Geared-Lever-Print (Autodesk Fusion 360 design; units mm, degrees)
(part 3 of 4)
sketch "Restore cam service opening after obsolete bore closure" plane through (23.9, 0, 0) normal (1, 0, 0) x axis (0, 0, -1)
  line L1 (-42.2047, 46.7373) -> (-43.8497, 47.5044)
  line L2 (-40.5875, 45.9133) -> (-42.2047, 46.7373)
  line L3 (-39, 45.0333) -> (-40.5875, 45.9133)
  line L4 (-37.4442, 44.0985) -> (-39, 45.0333)
  line L5 (-35.922, 43.11) -> (-37.4442, 44.0985)
  line L6 (-34.4352, 42.0689) -> (-35.922, 43.11)
  line L7 (-32.9856, 40.9766) -> (-34.4352, 42.0689)
  line L8 (-31.575, 39.8343) -> (-32.9856, 40.9766)
  line L9 (-30.2052, 38.6435) -> (-31.575, 39.8343)
  line L10 (-28.8778, 37.4057) -> (-30.2052, 38.6435)
  line L11 (-27.5943, 36.1222) -> (-28.8778, 37.4057)
  line L12 (-26.3565, 34.7948) -> (-27.5943, 36.1222)
  line L13 (-25.1657, 33.425) -> (-26.3565, 34.7948)
  line L14 (-24.0234, 32.0144) -> (-25.1657, 33.425)
  line L15 (-22.9311, 30.5648) -> (-24.0234, 32.0144)
  line L16 (-21.89, 29.078) -> (-22.9311, 30.5648)
  line L17 (-20.9015, 27.5558) -> (-21.89, 29.078)
  line L18 (-19.9667, 26) -> (-20.9015, 27.5558)
  line L19 (-19.0867, 24.4125) -> (-19.9667, 26)
  line L20 (-18.2627, 22.7953) -> (-19.0867, 24.4125)
  line L21 (-17.4956, 21.1503) -> (-18.2627, 22.7953)
  line L22 (-16.7864, 19.4795) -> (-17.4956, 21.1503)
  line L23 (-16.136, 17.785) -> (-16.7864, 19.4795)
  line L24 (-15.5451, 16.0689) -> (-16.136, 17.785)
  line L25 (-15.0144, 14.3331) -> (-15.5451, 16.0689)
  line L26 (-14.5446, 12.5799) -> (-15.0144, 14.3331)
  line L27 (-14.1363, 10.8114) -> (-14.5446, 12.5799)
  line L28 (-13.79, 9.0297) -> (-14.1363, 10.8114)
  line L29 (-13.5061, 7.237) -> (-13.79, 9.0297)
  line L30 (-13.2849, 5.4355) -> (-13.5061, 7.237)
  line L31 (-13.1267, 3.6273) -> (-13.2849, 5.4355)
  line L32 (-13.0317, 1.8148) -> (-13.1267, 3.6273)
  line L33 (-13, 0) -> (-13.0317, 1.8148)
  line L34 (-13.0317, -1.8148) -> (-13, 0)
  line L35 (-13.1267, -3.6273) -> (-13.0317, -1.8148)
  line L36 (-13.2849, -5.4355) -> (-13.1267, -3.6273)
  line L37 (-13.5061, -7.237) -> (-13.2849, -5.4355)
  line L38 (-13.79, -9.0297) -> (-13.5061, -7.237)
  line L39 (-14.1363, -10.8114) -> (-13.79, -9.0297)
  line L40 (-14.5446, -12.5799) -> (-14.1363, -10.8114)
  line L41 (-15.0144, -14.3331) -> (-14.5446, -12.5799)
  line L42 (-15.5451, -16.0689) -> (-15.0144, -14.3331)
  line L43 (-16.136, -17.785) -> (-15.5451, -16.0689)
  line L44 (-16.7864, -19.4795) -> (-16.136, -17.785)
  line L45 (-17.4956, -21.1503) -> (-16.7864, -19.4795)
  line L46 (-18.2627, -22.7953) -> (-17.4956, -21.1503)
  line L47 (-19.0867, -24.4125) -> (-18.2627, -22.7953)
  line L48 (-19.9667, -26) -> (-19.0867, -24.4125)
  line L49 (-20.9015, -27.5558) -> (-19.9667, -26)
  line L50 (-21.89, -29.078) -> (-20.9015, -27.5558)
  line L51 (-22.9311, -30.5648) -> (-21.89, -29.078)
  line L52 (-24.0234, -32.0144) -> (-22.9311, -30.5648)
  line L53 (-25.1657, -33.425) -> (-24.0234, -32.0144)
  line L54 (-26.3565, -34.7948) -> (-25.1657, -33.425)
  line L55 (-27.5943, -36.1222) -> (-26.3565, -34.7948)
  line L56 (-28.8778, -37.4057) -> (-27.5943, -36.1222)
  line L57 (-30.2052, -38.6435) -> (-28.8778, -37.4057)
  line L58 (-31.575, -39.8343) -> (-30.2052, -38.6435)
  line L59 (-32.9856, -40.9766) -> (-31.575, -39.8343)
  line L60 (-34.4352, -42.0689) -> (-32.9856, -40.9766)
  line L61 (-35.922, -43.11) -> (-34.4352, -42.0689)
  line L62 (-37.4442, -44.0985) -> (-35.922, -43.11)
  line L63 (-39, -45.0333) -> (-37.4442, -44.0985)
  line L64 (-40.5875, -45.9133) -> (-39, -45.0333)
  line L65 (-42.2047, -46.7373) -> (-40.5875, -45.9133)
  line L66 (-43.8497, -47.5044) -> (-42.2047, -46.7373)
  line L67 (-54.4248, -23.7522) -> (-43.8497, -47.5044)
  line L68 (-53.6024, -23.3686) -> (-54.4248, -23.7522)
  line L69 (-52.7937, -22.9566) -> (-53.6024, -23.3686)
  line L70 (-52, -22.5167) -> (-52.7937, -22.9566)
  line L71 (-51.2221, -22.0493) -> (-52, -22.5167)
  line L72 (-50.461, -21.555) -> (-51.2221, -22.0493)
  line L73 (-49.7176, -21.0344) -> (-50.461, -21.555)
  line L74 (-48.9928, -20.4883) -> (-49.7176, -21.0344)
  line L75 (-48.2875, -19.9172) -> (-48.9928, -20.4883)
  line L76 (-47.6026, -19.3218) -> (-48.2875, -19.9172)
  line L77 (-46.9389, -18.7028) -> (-47.6026, -19.3218)
  line L78 (-46.2972, -18.0611) -> (-46.9389, -18.7028)
  line L79 (-45.6782, -17.3974) -> (-46.2972, -18.0611)
  line L80 (-45.0828, -16.7125) -> (-45.6782, -17.3974)
  line L81 (-44.5117, -16.0072) -> (-45.0828, -16.7125)
  line L82 (-43.9656, -15.2824) -> (-44.5117, -16.0072)
  line L83 (-43.445, -14.539) -> (-43.9656, -15.2824)
  line L84 (-42.9507, -13.7779) -> (-43.445, -14.539)
  line L85 (-42.4833, -13) -> (-42.9507, -13.7779)
  line L86 (-42.0434, -12.2063) -> (-42.4833, -13)
  line L87 (-41.6314, -11.3976) -> (-42.0434, -12.2063)
  line L88 (-41.2478, -10.5752) -> (-41.6314, -11.3976)
  line L89 (-40.8932, -9.7398) -> (-41.2478, -10.5752)
  line L90 (-40.568, -8.8925) -> (-40.8932, -9.7398)
  line L91 (-40.2725, -8.0344) -> (-40.568, -8.8925)
  line L92 (-40.0072, -7.1666) -> (-40.2725, -8.0344)
  line L93 (-39.7723, -6.29) -> (-40.0072, -7.1666)
  line L94 (-39.5682, -5.4057) -> (-39.7723, -6.29)
  line L95 (-39.395, -4.5149) -> (-39.5682, -5.4057)
  line L96 (-39.253, -3.6185) -> (-39.395, -4.5149)
  line L97 (-39.1424, -2.7177) -> (-39.253, -3.6185)
  line L98 (-39.0633, -1.8137) -> (-39.1424, -2.7177)
  line L99 (-39.0158, -0.9074) -> (-39.0633, -1.8137)
  line L100 (-39, 0) -> (-39.0158, -0.9074)
  line L101 (-39.0158, 0.9074) -> (-39, 0)
  line L102 (-39.0633, 1.8137) -> (-39.0158, 0.9074)
  line L103 (-39.1424, 2.7177) -> (-39.0633, 1.8137)
  line L104 (-39.253, 3.6185) -> (-39.1424, 2.7177)
  line L105 (-39.395, 4.5149) -> (-39.253, 3.6185)
  line L106 (-39.5682, 5.4057) -> (-39.395, 4.5149)
  line L107 (-39.7723, 6.29) -> (-39.5682, 5.4057)
  line L108 (-40.0072, 7.1666) -> (-39.7723, 6.29)
  line L109 (-40.2725, 8.0344) -> (-40.0072, 7.1666)
  line L110 (-40.568, 8.8925) -> (-40.2725, 8.0344)
  line L111 (-40.8932, 9.7398) -> (-40.568, 8.8925)
  line L112 (-41.2478, 10.5752) -> (-40.8932, 9.7398)
  line L113 (-41.6314, 11.3976) -> (-41.2478, 10.5752)
  line L114 (-42.0434, 12.2063) -> (-41.6314, 11.3976)
  line L115 (-42.4833, 13) -> (-42.0434, 12.2063)
  line L116 (-42.9507, 13.7779) -> (-42.4833, 13)
  line L117 (-43.445, 14.539) -> (-42.9507, 13.7779)
  line L118 (-43.9656, 15.2824) -> (-43.445, 14.539)
  line L119 (-44.5117, 16.0072) -> (-43.9656, 15.2824)
  line L120 (-45.0828, 16.7125) -> (-44.5117, 16.0072)
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extrude "Extrude47" cut sketch "Restore cam service opening after obsolete bore closure" along normal blind 12.2
work_plane "WorkPlane48" AlongDistance -15.4 ExtraOffset 0
sketch "Fill former M5 stop nut pocket" plane through (-15.4, 0, 0) normal (1, 0, 0) x axis (0, 0, -1)
  circle C1 centre (-79.6754, -33.9652) radius 4.9
extrude "Extrude48" add sketch "Fill former M5 stop nut pocket" along normal blind 6.4
work_plane "WorkPlane49" AlongDistance -36 ExtraOffset 0
sketch "Fill former M5 stop bore" plane through (-36, 0, 0) normal (1, 0, 0) x axis (0, 0, -1)
  circle C1 centre (-79.6754, -33.9652) radius 2.71
extrude "Extrude49" add sketch "Fill former M5 stop bore" along normal blind 27
work_plane "WorkPlane50" AlongDistance -36.1 ExtraOffset 0
sketch "M3 stop reinforcement bore" plane through (-36.1, 0, 0) normal (1, 0, 0) x axis (0, 0, -1)
  circle C1 centre (-79.6754, -33.9652) radius 1.7
extrude "Extrude50" cut sketch "M3 stop reinforcement bore" along normal blind 27.2
work_plane "WorkPlane51" AlongDistance -13.5 ExtraOffset 0
sketch "Captive M3 locknut stop pocket" plane through (-13.5, 0, 0) normal (1, 0, 0) x axis (0, 0, -1)
  line L1 (-82.5754, -32.2908) -> (-79.6754, -30.6165)
  line L2 (-82.5754, -35.6395) -> (-82.5754, -32.2908)
  line L3 (-79.6754, -37.3138) -> (-82.5754, -35.6395)
  line L4 (-76.7754, -35.6395) -> (-79.6754, -37.3138)
  line L5 (-76.7754, -32.2908) -> (-76.7754, -35.6395)
  line L6 (-79.6754, -30.6165) -> (-76.7754, -32.2908)
extrude "Extrude51" cut sketch "Captive M3 locknut stop pocket" along normal blind 4.6
work_plane "WorkPlane52" AlongDistance -15.4 ExtraOffset 0
sketch "Fill former M5 stop nut pocket (1)" plane through (-15.4, 0, 0) normal (1, 0, 0) x axis (0, 0, -1)
  circle C1 centre (-79.6754, 33.9652) radius 4.9
extrude "Extrude52" add sketch "Fill former M5 stop nut pocket (1)" along normal blind 6.4
work_plane "WorkPlane53" AlongDistance -36 ExtraOffset 0
sketch "Fill former M5 stop bore (1)" plane through (-36, 0, 0) normal (1, 0, 0) x axis (0, 0, -1)
  circle C1 centre (-79.6754, 33.9652) radius 2.71
extrude "Extrude53" add sketch "Fill former M5 stop bore (1)" along normal blind 27
work_plane "WorkPlane54" AlongDistance -36.1 ExtraOffset 0
sketch "M3 stop reinforcement bore (1)" plane through (-36.1, 0, 0) normal (1, 0, 0) x axis (0, 0, -1)
  circle C1 centre (-79.6754, 33.9652) radius 1.7
extrude "Extrude54" cut sketch "M3 stop reinforcement bore (1)" along normal blind 27.2
work_plane "WorkPlane55" AlongDistance -13.5 ExtraOffset 0
sketch "Captive M3 locknut stop pocket (1)" plane through (-13.5, 0, 0) normal (1, 0, 0) x axis (0, 0, -1)
  line L1 (-82.5754, 35.6395) -> (-79.6754, 37.3138)
  line L2 (-82.5754, 32.2908) -> (-82.5754, 35.6395)
  line L3 (-79.6754, 30.6165) -> (-82.5754, 32.2908)
  line L4 (-76.7754, 32.2908) -> (-79.6754, 30.6165)
  line L5 (-76.7754, 35.6395) -> (-76.7754, 32.2908)
  line L6 (-79.6754, 37.3138) -> (-76.7754, 35.6395)
extrude "Extrude55" cut sketch "Captive M3 locknut stop pocket (1)" along normal blind 4.6
work_plane "WorkPlane56" AlongDistance -17.5 ExtraOffset 0
sketch "Recess M3 locknut to keep bolt inside stop" plane through (-17.5, 0, 0) normal (1, 0, 0) x axis (0, 0, -1)
  line L1 (-82.5754, -32.2908) -> (-79.6754, -30.6165)
  line L2 (-82.5754, -35.6395) -> (-82.5754, -32.2908)
  line L3 (-79.6754, -37.3138) -> (-82.5754, -35.6395)
  line L4 (-76.7754, -35.6395) -> (-79.6754, -37.3138)
  line L5 (-76.7754, -32.2908) -> (-76.7754, -35.6395)
  line L6 (-79.6754, -30.6165) -> (-76.7754, -32.2908)
extrude "Extrude56" cut sketch "Recess M3 locknut to keep bolt inside stop" along normal blind 4.01
work_plane "WorkPlane57" AlongDistance -17.5 ExtraOffset 0
sketch "Recess M3 locknut to keep bolt inside stop (1)" plane through (-17.5, 0, 0) normal (1, 0, 0) x axis (0, 0, -1)
  line L1 (-82.5754, 35.6395) -> (-79.6754, 37.3138)
  line L2 (-82.5754, 32.2908) -> (-82.5754, 35.6395)
  line L3 (-79.6754, 30.6165) -> (-82.5754, 32.2908)
  line L4 (-76.7754, 32.2908) -> (-79.6754, 30.6165)
  line L5 (-76.7754, 35.6395) -> (-76.7754, 32.2908)
  line L6 (-79.6754, 37.3138) -> (-76.7754, 35.6395)
extrude "Extrude57" cut sketch "Recess M3 locknut to keep bolt inside stop (1)" along normal blind 4.01
work_plane "WorkPlane6" AlongDistance -7.2 ExtraOffset 0
sketch "Upright socket roof 45 degrees" plane through (0, -7.2, 0) normal (0, 1, 0) x axis (1, 0, 0)
  line L1 (-7.2, -196) -> (0, -196)
  line L2 (0, -203.2) -> (-7.2, -196)
  line L3 (0, -196) -> (0, -203.2)
extrude "Extrude5" cut sketch "Upright socket roof 45 degrees" along normal blind 14.4
work_plane "WorkPlane8" AlongDistance -7.2 ExtraOffset 0
sketch "Upright socket roof 45 degrees" plane through (0, -7.2, 0) normal (0, 1, 0) x axis (1, 0, 0)
  line L1 (7.2, -196) -> (0, -196)
  line L2 (0, -203.2) -> (7.2, -196)
  line L3 (0, -196) -> (0, -203.2)
extrude "Extrude7" cut sketch "Upright socket roof 45 degrees" along normal blind 14.4
work_plane "WorkPlane58" AlongDistance -36 ExtraOffset 0
sketch "Stock M5x14 mounting seat Z64" plane through (-36, 0, 0) normal (1, 0, 0) x axis (0, 0, -1)
  line L1 (-63, -70) -> (-63, -95)
  line L2 (-64, -70) -> (-63, -70)
  line L3 (-64, -95) -> (-64, -70)
  line L4 (-63, -95) -> (-64, -95)
extrude "Extrude58" add sketch "Stock M5x14 mounting seat Z64" along normal blind 12
work_plane "WorkPlane59" AlongDistance 62.9 ExtraOffset 0
sketch "Continue rail clearance through new seat" plane through (0, 0, 62.9) normal (0, 0, 1) x axis (1, 0, 0)
  circle C1 centre (-30, -85) radius 2.7
extrude "Extrude59" cut sketch "Continue rail clearance through new seat" along normal blind 1.2
work_plane "WorkPlane1" AlongDistance 50 ExtraOffset 0
sketch "Rail M5x14 DIN912 (-30, -1)" plane through (0, 0, 50) normal (0, 0, 1) x axis (1, 0, 0)
  circle C1 centre (-30, -85) radius 2.5
extrude "Extrude1" new body sketch "Rail M5x14 DIN912 (-30, -1)" along normal blind 14 bodies "HARDWARE Rail M5x14 DIN912 (-30, -1)"
work_plane "WorkPlane2" AlongDistance 64 ExtraOffset 0
sketch "Button head" plane through (0, 0, 64) normal (0, 0, 1) x axis (1, 0, 0)
  circle C1 centre (-30, -85) radius 4.25
extrude "Extrude2" add sketch "Button head" along normal blind 5
work_plane "WorkPlane60" AlongDistance -36 ExtraOffset 0
sketch "Stock M5x14 mounting seat Z64 (1)" plane through (-36, 0, 0) normal (1, 0, 0) x axis (0, 0, -1)
  line L1 (-63, 95) -> (-63, 70)
  line L2 (-64, 95) -> (-63, 95)
  line L3 (-64, 70) -> (-64, 95)
  line L4 (-63, 70) -> (-64, 70)
extrude "Extrude60" add sketch "Stock M5x14 mounting seat Z64 (1)" along normal blind 12
work_plane "WorkPlane61" AlongDistance 62.9 ExtraOffset 0
sketch "Continue rail clearance through new seat (1)" plane through (0, 0, 62.9) normal (0, 0, 1) x axis (1, 0, 0)
  circle C1 centre (-30, 85) radius 2.7
extrude "Extrude61" cut sketch "Continue rail clearance through new seat (1)" along normal blind 1.2
work_plane "WorkPlane1" AlongDistance 50 ExtraOffset 0
sketch "Rail M5x14 DIN912 (-30, 1)" plane through (0, 0, 50) normal (0, 0, 1) x axis (1, 0, 0)
  circle C1 centre (-30, 85) radius 2.5
extrude "Extrude1" new body sketch "Rail M5x14 DIN912 (-30, 1)" along normal blind 14 bodies "HARDWARE Rail M5x14 DIN912 (-30, 1)"
work_plane "WorkPlane2" AlongDistance 64 ExtraOffset 0
sketch "Button head" plane through (0, 0, 64) normal (0, 0, 1) x axis (1, 0, 0)
  circle C1 centre (-30, 85) radius 4.25
extrude "Extrude2" add sketch "Button head" along normal blind 5
work_plane "WorkPlane62" AlongDistance -36 ExtraOffset 0
sketch "Close obsolete long pivot screw hole" plane through (-36, 0, 0) normal (1, 0, 0) x axis (0, 0, -1)
  circle C1 centre (-12, -35) radius 1.71
extrude "Extrude62" add sketch "Close obsolete long pivot screw hole" along normal blind 12
work_plane "WorkPlane63" AlongDistance -26 ExtraOffset 0
sketch "Blind captive printed pivot seat" plane through (-26, 0, 0) normal (1, 0, 0) x axis (0, 0, -1)
  circle C1 centre (-12, -35) radius 4.15
extrude "Extrude63" cut sketch "Blind captive printed pivot seat" along normal blind 2.1
work_plane "WorkPlane48" AlongDistance 24 ExtraOffset 0
sketch "Stock M5x14 mounting seat Z64" plane through (24, 0, 0) normal (1, 0, 0) x axis (0, 0, -1)
  line L1 (-63, -70) -> (-63, -95)
  line L2 (-64, -70) -> (-63, -70)
  line L3 (-64, -95) -> (-64, -70)
  line L4 (-63, -95) -> (-64, -95)
extrude "Extrude48" add sketch "Stock M5x14 mounting seat Z64" along normal blind 12
work_plane "WorkPlane49" AlongDistance 62.9 ExtraOffset 0
sketch "Continue rail clearance through new seat" plane through (0, 0, 62.9) normal (0, 0, 1) x axis (1, 0, 0)
  circle C1 centre (30, -85) radius 2.7
extrude "Extrude49" cut sketch "Continue rail clearance through new seat" along normal blind 1.2
work_plane "WorkPlane1" AlongDistance 50 ExtraOffset 0
sketch "Rail M5x14 DIN912 (30, -1)" plane through (0, 0, 50) normal (0, 0, 1) x axis (1, 0, 0)
  circle C1 centre (30, -85) radius 2.5
extrude "Extrude1" new body sketch "Rail M5x14 DIN912 (30, -1)" along normal blind 14 bodies "HARDWARE Rail M5x14 DIN912 (30, -1)"
work_plane "WorkPlane2" AlongDistance 64 ExtraOffset 0
sketch "Button head" plane through (0, 0, 64) normal (0, 0, 1) x axis (1, 0, 0)
  circle C1 centre (30, -85) radius 4.25
extrude "Extrude2" add sketch "Button head" along normal blind 5
work_plane "WorkPlane50" AlongDistance 24 ExtraOffset 0
sketch "Stock M5x14 mounting seat Z64 (1)" plane through (24, 0, 0) normal (1, 0, 0) x axis (0, 0, -1)
  line L1 (-63, 95) -> (-63, 70)
  line L2 (-64, 95) -> (-63, 95)
  line L3 (-64, 70) -> (-64, 95)
  line L4 (-63, 70) -> (-64, 70)
extrude "Extrude50" add sketch "Stock M5x14 mounting seat Z64 (1)" along normal blind 12
work_plane "WorkPlane51" AlongDistance 62.9 ExtraOffset 0
sketch "Continue rail clearance through new seat (1)" plane through (0, 0, 62.9) normal (0, 0, 1) x axis (1, 0, 0)
  circle C1 centre (30, 85) radius 2.7
extrude "Extrude51" cut sketch "Continue rail clearance through new seat (1)" along normal blind 1.2
work_plane "WorkPlane1" AlongDistance 50 ExtraOffset 0
sketch "Rail M5x14 DIN912 (30, 1)" plane through (0, 0, 50) normal (0, 0, 1) x axis (1, 0, 0)
  circle C1 centre (30, 85) radius 2.5
extrude "Extrude1" new body sketch "Rail M5x14 DIN912 (30, 1)" along normal blind 14 bodies "HARDWARE Rail M5x14 DIN912 (30, 1)"
work_plane "WorkPlane2" AlongDistance 64 ExtraOffset 0
sketch "Button head" plane through (0, 0, 64) normal (0, 0, 1) x axis (1, 0, 0)
  circle C1 centre (30, 85) radius 4.25
extrude "Extrude2" add sketch "Button head" along normal blind 5
work_plane "WorkPlane52" AlongDistance 24 ExtraOffset 0
sketch "Close obsolete long pivot screw hole" plane through (24, 0, 0) normal (1, 0, 0) x axis (0, 0, -1)
  circle C1 centre (-12, -35) radius 1.71
extrude "Extrude52" add sketch "Close obsolete long pivot screw hole" along normal blind 12
work_plane "WorkPlane53" AlongDistance 23.9 ExtraOffset 0
sketch "Blind captive printed pivot seat" plane through (23.9, 0, 0) normal (1, 0, 0) x axis (0, 0, -1)
  circle C1 centre (-12, -35) radius 4.15
extrude "Extrude53" cut sketch "Blind captive printed pivot seat" along normal blind 2.1
work_plane "WorkPlane1" AlongDistance -25.85 ExtraOffset 0
sketch "Captured axle 0.3 mm total end clearance" plane through (-25.85, 0, 0) normal (1, 0, 0) x axis (0, 0, -1)
  circle C1 centre (-12, -35) radius 4
extrude "Extrude1" new body sketch "Captured axle 0.3 mm total end clearance" along normal blind 51.7 bodies "P25 Captured printed pivot lower half"
work_plane "WorkPlane2" AlongDistance -26 ExtraOffset 0
sketch "Longitudinal flat print face" plane through (-26, 0, 0) normal (1, 0, 0) x axis (0, 0, -1)
  line L1 (-7, -30) -> (-7, -35)
  line L2 (-17, -30) -> (-7, -30)
  line L3 (-17, -35) -> (-17, -30)
  line L4 (-7, -35) -> (-17, -35)
extrude "Extrude2" cut sketch "Longitudinal flat print face" along normal blind 52
work_plane "WorkPlane1" AlongDistance -25.85 ExtraOffset 0
sketch "Captured axle 0.3 mm total end clearance" plane through (-25.85, 0, 0) normal (1, 0, 0) x axis (0, 0, -1)
  circle C1 centre (-12, -35) radius 4
extrude "Extrude1" new body sketch "Captured axle 0.3 mm total end clearance" along normal blind 51.7 bodies "P26 Captured printed pivot upper half"
work_plane "WorkPlane2" AlongDistance -26 ExtraOffset 0
sketch "Longitudinal flat print face" plane through (-26, 0, 0) normal (1, 0, 0) x axis (0, 0, -1)
  line L1 (-7, -35) -> (-7, -40)
  line L2 (-17, -35) -> (-7, -35)
  line L3 (-17, -40) -> (-17, -35)
  line L4 (-7, -40) -> (-17, -40)
extrude "Extrude2" cut sketch "Longitudinal flat print face" along normal blind 52
work_plane "WorkPlane9" AlongDistance 9 ExtraOffset 0
sketch "Recess for stocked M3x20 grip screw" plane through (9, 0, 0) normal (1, 0, 0) x axis (0, 0, -1)
  circle C1 centre (-180, 0) radius 3.1
extrude "Extrude8" cut sketch "Recess for stocked M3x20 grip screw" along normal blind 3.6
work_plane "WorkPlane1" AlongDistance -11 ExtraOffset 0
sketch "Grip M3x20 cap head 180" plane through (-11, 0, 0) normal (1, 0, 0) x axis (0, 0, -1)
  circle C1 centre (-180, 0) radius 1.5
extrude "Extrude1" new body sketch "Grip M3x20 cap head 180" along normal blind 20 bodies "HARDWARE Grip M3x20 cap head 180"
work_plane "WorkPlane2" AlongDistance 9 ExtraOffset 0
sketch "Button head" plane through (9, 0, 0) normal (1, 0, 0) x axis (0, 0, -1)
  circle C1 centre (-180, 0) radius 2.75
extrude "Extrude2" add sketch "Button head" along normal blind 3
work_plane "WorkPlane10" AlongDistance 9 ExtraOffset 0
sketch "Recess for stocked M3x20 grip screw (1)" plane through (9, 0, 0) normal (1, 0, 0) x axis (0, 0, -1)
  circle C1 centre (-190, 0) radius 3.1
extrude "Extrude9" cut sketch "Recess for stocked M3x20 grip screw (1)" along normal blind 3.6
work_plane "WorkPlane1" AlongDistance -11 ExtraOffset 0
sketch "Grip M3x20 cap head 190" plane through (-11, 0, 0) normal (1, 0, 0) x axis (0, 0, -1)
  circle C1 centre (-190, 0) radius 1.5
extrude "Extrude1" new body sketch "Grip M3x20 cap head 190" along normal blind 20 bodies "HARDWARE Grip M3x20 cap head 190"
work_plane "WorkPlane2" AlongDistance 9 ExtraOffset 0
sketch "Button head" plane through (9, 0, 0) normal (1, 0, 0) x axis (0, 0, -1)
  circle C1 centre (-190, 0) radius 2.75
extrude "Extrude2" add sketch "Button head" along normal blind 3
work_plane "WorkPlane64" AlongDistance -36.1 ExtraOffset 0
sketch "Stock M3x20 stop recessed cap head" plane through (-36.1, 0, 0) normal (1, 0, 0) x axis (0, 0, -1)
  circle C1 centre (-79.6754, -33.9652) radius 3.1
extrude "Extrude64" cut sketch "Stock M3x20 stop recessed cap head" along normal blind 4.6
work_plane "WorkPlane1" AlongDistance -31.5 ExtraOffset 0
sketch "Stop M3x20 cap head -1" plane through (-31.5, 0, 0) normal (1, 0, 0) x axis (0, 0, -1)
  circle C1 centre (-79.6754, -33.9652) radius 1.5
extrude "Extrude1" new body sketch "Stop M3x20 cap head -1" along normal blind 20 bodies "HARDWARE Stop M3x20 cap head -1"
work_plane "WorkPlane2" AlongDistance -34.5 ExtraOffset 0
sketch "Button head" plane through (-34.5, 0, 0) normal (1, 0, 0) x axis (0, 0, -1)
  circle C1 centre (-79.6754, -33.9652) radius 2.75
extrude "Extrude2" add sketch "Button head" along normal blind 3
work_plane "WorkPlane1" AlongDistance -17.5 ExtraOffset 0
sketch "Stop M3 plain captive nut -1" plane through (-17.5, 0, 0) normal (1, 0, 0) x axis (0, 0, -1)
  line L1 (-82.4254, -32.3774) -> (-79.6754, -30.7897)
  line L2 (-82.4254, -35.5529) -> (-82.4254, -32.3774)
  line L3 (-79.6754, -37.1406) -> (-82.4254, -35.5529)
  line L4 (-76.9254, -35.5529) -> (-79.6754, -37.1406)
  line L5 (-76.9254, -32.3774) -> (-76.9254, -35.5529)
  line L6 (-79.6754, -30.7897) -> (-76.9254, -32.3774)
extrude "Extrude1" new body sketch "Stop M3 plain captive nut -1" along normal blind 2.4 bodies "HARDWARE Stop M3 plain captive nut -1"
work_plane "WorkPlane2" AlongDistance -17.6 ExtraOffset 0
sketch "Thread envelope" plane through (-17.6, 0, 0) normal (1, 0, 0) x axis (0, 0, -1)
  circle C1 centre (-79.6754, -33.9652) radius 1.5
extrude "Extrude2" cut sketch "Thread envelope" along normal blind 2.6
work_plane "WorkPlane65" AlongDistance -36.1 ExtraOffset 0
sketch "Stock M3x20 stop recessed cap head (1)" plane through (-36.1, 0, 0) normal (1, 0, 0) x axis (0, 0, -1)
  circle C1 centre (-79.6754, 33.9652) radius 3.1
extrude "Extrude65" cut sketch "Stock M3x20 stop recessed cap head (1)" along normal blind 4.6
work_plane "WorkPlane1" AlongDistance -31.5 ExtraOffset 0
sketch "Stop M3x20 cap head 1" plane through (-31.5, 0, 0) normal (1, 0, 0) x axis (0, 0, -1)
  circle C1 centre (-79.6754, 33.9652) radius 1.5
extrude "Extrude1" new body sketch "Stop M3x20 cap head 1" along normal blind 20 bodies "HARDWARE Stop M3x20 cap head 1"
work_plane "WorkPlane2" AlongDistance -34.5 ExtraOffset 0
sketch "Button head" plane through (-34.5, 0, 0) normal (1, 0, 0) x axis (0, 0, -1)
  circle C1 centre (-79.6754, 33.9652) radius 2.75
extrude "Extrude2" add sketch "Button head" along normal blind 3
work_plane "WorkPlane1" AlongDistance -17.5 ExtraOffset 0
sketch "Stop M3 plain captive nut 1" plane through (-17.5, 0, 0) normal (1, 0, 0) x axis (0, 0, -1)
  line L1 (-82.4254, 35.5529) -> (-79.6754, 37.1406)
  line L2 (-82.4254, 32.3774) -> (-82.4254, 35.5529)
  line L3 (-79.6754, 30.7897) -> (-82.4254, 32.3774)
  line L4 (-76.9254, 32.3774) -> (-79.6754, 30.7897)
  line L5 (-76.9254, 35.5529) -> (-76.9254, 32.3774)
  line L6 (-79.6754, 37.1406) -> (-76.9254, 35.5529)
extrude "Extrude1" new body sketch "Stop M3 plain captive nut 1" along normal blind 2.4 bodies "HARDWARE Stop M3 plain captive nut 1"
work_plane "WorkPlane2" AlongDistance -17.6 ExtraOffset 0
sketch "Thread envelope" plane through (-17.6, 0, 0) normal (1, 0, 0) x axis (0, 0, -1)
  circle C1 centre (-79.6754, 33.9652) radius 1.5
extrude "Extrude2" cut sketch "Thread envelope" along normal blind 2.6
work_plane "WorkPlane10" AlongDistance 7 ExtraOffset 0
sketch "Bearing inner race support pad" plane through (7, 0, 0) normal (1, 0, 0) x axis (0, 0, -1)
  circle C1 centre (-12, 0) radius 2.4
extrude "Extrude10" add sketch "Bearing inner race support pad" along normal blind 1
work_plane "WorkPlane11" AlongDistance 6.9 ExtraOffset 0
sketch "Preserve roller screw clearance" plane through (6.9, 0, 0) normal (1, 0, 0) x axis (0, 0, -1)
  circle C1 centre (-12, 0) radius 1.7
extrude "Extrude11" cut sketch "Preserve roller screw clearance" along normal blind 1.2
work_plane "WorkPlane12" AlongDistance 16 ExtraOffset 0
sketch "Bearing inner race support pad (1)" plane through (16, 0, 0) normal (1, 0, 0) x axis (0, 0, -1)
  circle C1 centre (-12, 0) radius 2.4
extrude "Extrude12" add sketch "Bearing inner race support pad (1)" along normal blind 1
work_plane "WorkPlane13" AlongDistance 15.9 ExtraOffset 0
sketch "Preserve roller screw clearance (1)" plane through (15.9, 0, 0) normal (1, 0, 0) x axis (0, 0, -1)
  circle C1 centre (-12, 0) radius 1.7
extrude "Extrude13" cut sketch "Preserve roller screw clearance (1)" along normal blind 1.2
work_plane "WorkPlane1" AlongDistance 8 ExtraOffset 0
sketch "Stock 623ZZ envelope 3x10x4" plane through (8, 0, 0) normal (1, 0, 0) x axis (0, 0, -1)
  circle C1 centre (-12, 0) radius 5
extrude "Extrude1" new body sketch "Stock 623ZZ envelope 3x10x4" along normal blind 4 bodies "HARDWARE 623ZZ roller bearing at 8"
work_plane "WorkPlane2" AlongDistance 7.9 ExtraOffset 0
sketch "Bearing inner race bore" plane through (7.9, 0, 0) normal (1, 0, 0) x axis (0, 0, -1)
  circle C1 centre (-12, 0) radius 1.5
extrude "Extrude2" cut sketch "Bearing inner race bore" along normal blind 4.2
work_plane "WorkPlane1" AlongDistance 12 ExtraOffset 0
sketch "Stock 623ZZ envelope 3x10x4" plane through (12, 0, 0) normal (1, 0, 0) x axis (0, 0, -1)
  circle C1 centre (-12, 0) radius 5
extrude "Extrude1" new body sketch "Stock 623ZZ envelope 3x10x4" along normal blind 4 bodies "HARDWARE 623ZZ roller bearing at 12"
work_plane "WorkPlane2" AlongDistance 11.9 ExtraOffset 0
sketch "Bearing inner race bore" plane through (11.9, 0, 0) normal (1, 0, 0) x axis (0, 0, -1)
  circle C1 centre (-12, 0) radius 1.5
extrude "Extrude2" cut sketch "Bearing inner race bore" along normal blind 4.2
work_plane "WorkPlane45" AlongDistance 38 ExtraOffset 0
sketch "Close former long guide bore" plane through (0, 0, 38) normal (0, 0, 1) x axis (1, 0, 0)
  circle C1 centre (5, -55) radius 1.71
extrude "Extrude45" add sketch "Close former long guide bore" along normal blind 21
work_plane "WorkPlane46" AlongDistance 38 ExtraOffset 0
sketch "Close former long guide bore (1)" plane through (0, 0, 38) normal (0, 0, 1) x axis (1, 0, 0)
  circle C1 centre (19, -55) radius 1.71
extrude "Extrude46" add sketch "Close former long guide bore (1)" along normal blind 21
work_plane "WorkPlane47" AlongDistance 38 ExtraOffset 0
sketch "Close obsolete M4 nut pocket" plane through (0, 0, 38) normal (0, 0, 1) x axis (1, 0, 0)
  line L1 (14.1362, -51.3) -> (16.2724, -55)
  line L2 (9.8638, -51.3) -> (14.1362, -51.3)
  line L3 (7.7276, -55) -> (9.8638, -51.3)
  line L4 (9.8638, -58.7) -> (7.7276, -55)
  line L5 (14.1362, -58.7) -> (9.8638, -58.7)
  line L6 (16.2724, -55) -> (14.1362, -58.7)
extrude "Extrude47" add sketch "Close obsolete M4 nut pocket" along normal blind 3.5
work_plane "WorkPlane48" AlongDistance 38 ExtraOffset 0
sketch "Close obsolete M4 adjuster passage" plane through (0, 0, 38) normal (0, 0, 1) x axis (1, 0, 0)
  circle C1 centre (12, -55) radius 2.21
extrude "Extrude48" add sketch "Close obsolete M4 adjuster passage" along normal blind 21
work_plane "WorkPlane49" AlongDistance 37.9 ExtraOffset 0
sketch "M3 preload adjuster passage" plane through (0, 0, 37.9) normal (0, 0, 1) x axis (1, 0, 0)
  circle C1 centre (12, -55) radius 1.7
extrude "Extrude49" cut sketch "M3 preload adjuster passage" along normal blind 21.2
work_plane "WorkPlane50" AlongDistance 37.9 ExtraOffset 0
sketch "M3 preload insert from spring side" plane through (0, 0, 37.9) normal (0, 0, 1) x axis (1, 0, 0)
  circle C1 centre (12, -55) radius 2
extrude "Extrude50" cut sketch "M3 preload insert from spring side" along normal blind 6.9
work_plane "WorkPlane51" AlongDistance 55 ExtraOffset 0
sketch "Recessed preload head and limiter access" plane through (0, 0, 55) normal (0, 0, 1) x axis (1, 0, 0)
  circle C1 centre (12, -55) radius 3.4
extrude "Extrude51" cut sketch "Recessed preload head and limiter access" along normal blind 4.1
work_plane "WorkPlane52" AlongDistance 37.9 ExtraOffset 0
sketch "Short guide M3 insert from underside" plane through (0, 0, 37.9) normal (0, 0, 1) x axis (1, 0, 0)
  circle C1 centre (4, -55) radius 2
extrude "Extrude52" cut sketch "Short guide M3 insert from underside" along normal blind 6.9
work_plane "WorkPlane1" AlongDistance 32 ExtraOffset 0
sketch "Short compression sleeve" plane through (0, 0, 32) normal (0, 0, 1) x axis (1, 0, 0)
  circle C1 centre (4, -55) radius 2.5
extrude "Extrude1" new body sketch "Short compression sleeve" along normal blind 6 bodies "P27 Printed guide sleeve 4"
work_plane "WorkPlane2" AlongDistance 31.9 ExtraOffset 0
sketch "Guide screw bore" plane through (0, 0, 31.9) normal (0, 0, 1) x axis (1, 0, 0)
  circle C1 centre (4, -55) radius 1.65
extrude "Extrude2" cut sketch "Guide screw bore" along normal blind 6.2
work_plane "WorkPlane1" AlongDistance 32 ExtraOffset 0
sketch "Cup guide M3x12 4" plane through (0, 0, 32) normal (0, 0, 1) x axis (1, 0, 0)
  circle C1 centre (4, -55) radius 1.5
extrude "Extrude1" new body sketch "Cup guide M3x12 4" along normal blind 12 bodies "HARDWARE Cup guide M3x12 4"
work_plane "WorkPlane2" AlongDistance 29 ExtraOffset 0
sketch "Button head" plane through (0, 0, 29) normal (0, 0, 1) x axis (1, 0, 0)
  circle C1 centre (4, -55) radius 2.75
extrude "Extrude2" add sketch "Button head" along normal blind 3
work_plane "WorkPlane53" AlongDistance 37.9 ExtraOffset 0
sketch "Short guide M3 insert from underside (1)" plane through (0, 0, 37.9) normal (0, 0, 1) x axis (1, 0, 0)
  circle C1 centre (20, -55) radius 2
extrude "Extrude53" cut sketch "Short guide M3 insert from underside (1)" along normal blind 6.9
work_plane "WorkPlane1" AlongDistance 32 ExtraOffset 0
sketch "Short compression sleeve" plane through (0, 0, 32) normal (0, 0, 1) x axis (1, 0, 0)
  circle C1 centre (20, -55) radius 2.5
extrude "Extrude1" new body sketch "Short compression sleeve" along normal blind 6 bodies "P27 Printed guide sleeve 20"
work_plane "WorkPlane2" AlongDistance 31.9 ExtraOffset 0
sketch "Guide screw bore" plane through (0, 0, 31.9) normal (0, 0, 1) x axis (1, 0, 0)
  circle C1 centre (20, -55) radius 1.65
extrude "Extrude2" cut sketch "Guide screw bore" along normal blind 6.2
work_plane "WorkPlane1" AlongDistance 32 ExtraOffset 0
sketch "Cup guide M3x12 20" plane through (0, 0, 32) normal (0, 0, 1) x axis (1, 0, 0)
  circle C1 centre (20, -55) radius 1.5
extrude "Extrude1" new body sketch "Cup guide M3x12 20" along normal blind 12 bodies "HARDWARE Cup guide M3x12 20"
work_plane "WorkPlane2" AlongDistance 29 ExtraOffset 0
sketch "Button head" plane through (0, 0, 29) normal (0, 0, 1) x axis (1, 0, 0)
  circle C1 centre (20, -55) radius 2.75
extrude "Extrude2" add sketch "Button head" along normal blind 3
work_plane "WorkPlane1" AlongDistance 0.2 ExtraOffset 0
sketch "Wide stock spring seat" plane through (0.2, 0, 0) normal (1, 0, 0) x axis (0, 0, -1)
  line L1 (-35, -49) -> (-35, -61)
  line L2 (-37, -49) -> (-35, -49)
  line L3 (-37, -61) -> (-37, -49)
  line L4 (-35, -61) -> (-37, -61)
extrude "Extrude1" new body sketch "Wide stock spring seat" along normal blind 23.6 bodies "P14 Captive spring cup for 9 mm spring"
work_plane "WorkPlane2" AlongDistance 29 ExtraOffset 0
sketch "Provisional 6 mm spring pilot" plane through (0, 0, 29) normal (0, 0, 1) x axis (1, 0, 0)
  circle C1 centre (12, -55) radius 3
extrude "Extrude2" add sketch "Provisional 6 mm spring pilot" along normal blind 6
work_plane "WorkPlane3" AlongDistance 34.9 ExtraOffset 0
sketch "Printed guide running clearance" plane through (0, 0, 34.9) normal (0, 0, 1) x axis (1, 0, 0)
  circle C1 centre (4, -55) radius 2.7
extrude "Extrude3" cut sketch "Printed guide running clearance" along normal blind 2.2
work_plane "WorkPlane4" AlongDistance 34.9 ExtraOffset 0
sketch "Printed guide running clearance (1)" plane through (0, 0, 34.9) normal (0, 0, 1) x axis (1, 0, 0)
  circle C1 centre (20, -55) radius 2.7
extrude "Extrude4" cut sketch "Printed guide running clearance (1)" along normal blind 2.2
work_plane "WorkPlane1" AlongDistance 55 ExtraOffset 0
sketch "Preserve one mm additional compression limit" plane through (0, 0, 55) normal (0, 0, 1) x axis (1, 0, 0)
  circle C1 centre (12, -55) radius 3.2
extrude "Extrude1" new body sketch "Preserve one mm additional compression limit" along normal blind 2 bodies "P15 Recessed preload limit collar 1 mm"
work_plane "WorkPlane2" AlongDistance 54.9 ExtraOffset 0
sketch "M3 adjuster clearance" plane through (0, 0, 54.9) normal (0, 0, 1) x axis (1, 0, 0)
  circle C1 centre (12, -55) radius 1.7
extrude "Extrude2" cut sketch "M3 adjuster clearance" along normal blind 2.2
work_plane "WorkPlane1" AlongDistance 37 ExtraOffset 0
sketch "Preload M3x20 cap head" plane through (0, 0, 37) normal (0, 0, 1) x axis (1, 0, 0)
  circle C1 centre (12, -55) radius 1.5
extrude "Extrude1" new body sketch "Preload M3x20 cap head" along normal blind 20 bodies "HARDWARE Preload M3x20 cap head"
work_plane "WorkPlane2" AlongDistance 57 ExtraOffset 0
sketch "Button head" plane through (0, 0, 57) normal (0, 0, 1) x axis (1, 0, 0)
  circle C1 centre (12, -55) radius 2.75
extrude "Extrude2" add sketch "Button head" along normal blind 3
work_plane "WorkPlane1" AlongDistance 18 ExtraOffset 0
sketch "Provisional stock spring installed envelope" plane through (0, 0, 18) normal (0, 0, 1) x axis (1, 0, 0)
  circle C1 centre (12, -55) radius 4.5
extrude "Extrude1" new body sketch "Provisional stock spring installed envelope" along normal blind 17 bodies "REFERENCE Stock spring OD9 wire1 free20 - rate and solid height assumed"
work_plane "WorkPlane2" AlongDistance 17.9 ExtraOffset 0
sketch "Stock spring nominal ID7" plane through (0, 0, 17.9) normal (0, 0, 1) x axis (1, 0, 0)
  circle C1 centre (12, -55) radius 3.5
extrude "Extrude2" cut sketch "Stock spring nominal ID7" along normal blind 17.2
work_plane "WorkPlane54" AlongDistance 36 ExtraOffset 0
sketch "Remove long sensor carriage supports" plane through (36, 0, 0) normal (1, 0, 0) x axis (0, 0, -1)
  line L1 (-46, 34) -> (-46, -34)
  line L2 (-84, 34) -> (-46, 34)
  line L3 (-84, -34) -> (-84, 34)
  line L4 (-46, -34) -> (-84, -34)
extrude "Extrude54" cut sketch "Remove long sensor carriage supports" along normal blind 44.1
work_plane "WorkPlane55" AlongDistance 36 ExtraOffset 0
sketch "Compact sensor support" plane through (36, 0, 0) normal (1, 0, 0) x axis (0, 0, -1)
  line L1 (-49, -18) -> (-49, -28)
  line L2 (-81, -18) -> (-49, -18)
  line L3 (-81, -28) -> (-81, -18)
  line L4 (-49, -28) -> (-81, -28)
extrude "Extrude55" add sketch "Compact sensor support" along normal blind 30.15
work_plane "WorkPlane56" AlongDistance -28.1 ExtraOffset 0
sketch "Compact carriage M3 insert" plane through (0, -28.1, 0) normal (0, 1, 0) x axis (1, 0, 0)
  circle C1 centre (60.15, -65) radius 2
extrude "Extrude56" cut sketch "Compact carriage M3 insert" along normal blind 6.8
work_plane "WorkPlane57" AlongDistance 36 ExtraOffset 0
sketch "Compact sensor support (1)" plane through (36, 0, 0) normal (1, 0, 0) x axis (0, 0, -1)
  line L1 (-49, 28) -> (-49, 18)
  line L2 (-81, 28) -> (-49, 28)
  line L3 (-81, 18) -> (-81, 28)
  line L4 (-49, 18) -> (-81, 18)
extrude "Extrude57" add sketch "Compact sensor support (1)" along normal blind 30.15
work_plane "WorkPlane58" AlongDistance 21.3 ExtraOffset 0
sketch "Compact carriage M3 insert (1)" plane through (0, 21.3, 0) normal (0, 1, 0) x axis (1, 0, 0)
  circle C1 centre (60.15, -65) radius 2
extrude "Extrude58" cut sketch "Compact carriage M3 insert (1)" along normal blind 6.8
work_plane "WorkPlane59" AlongDistance 36 ExtraOffset 0
sketch "Restore cam service path beneath compact rails" plane through (36, 0, 0) normal (1, 0, 0) x axis (0, 0, -1)
  line L1 (-48.9, -18) -> (-48.9, -28)
  line L2 (-56, -18) -> (-48.9, -18)
  line L3 (-56, -28) -> (-56, -18)
  line L4 (-48.9, -28) -> (-56, -28)
extrude "Extrude59" cut sketch "Restore cam service path beneath compact rails" along normal blind 30.25
work_plane "WorkPlane60" AlongDistance 36 ExtraOffset 0
sketch "Restore cam service path beneath compact rails (1)" plane through (36, 0, 0) normal (1, 0, 0) x axis (0, 0, -1)
  line L1 (-48.9, 28) -> (-48.9, 18)
  line L2 (-56, 28) -> (-48.9, 28)
  line L3 (-56, 18) -> (-56, 28)
  line L4 (-48.9, 18) -> (-56, 18)
extrude "Extrude60" cut sketch "Restore cam service path beneath compact rails (1)" along normal blind 30.25
work_plane "WorkPlane66" AlongDistance 54.9 ExtraOffset 0
sketch "Support-free horizontal rail hole roof" plane through (0, 0, 54.9) normal (0, 0, 1) x axis (1, 0, 0)
  line L1 (-28.0908, -83.0908) -> (-28.0908, -86.9092)
  line L2 (-26.1816, -85) -> (-28.0908, -83.0908)
  line L3 (-28.0908, -86.9092) -> (-26.1816, -85)
extrude "Extrude66" cut sketch "Support-free horizontal rail hole roof" along normal blind 9.2
work_plane "WorkPlane67" AlongDistance 54.9 ExtraOffset 0
sketch "Support-free horizontal rail hole roof (1)" plane through (0, 0, 54.9) normal (0, 0, 1) x axis (1, 0, 0)
  line L1 (-28.0908, 86.9092) -> (-28.0908, 83.0908)
  line L2 (-26.1816, 85) -> (-28.0908, 86.9092)
  line L3 (-28.0908, 83.0908) -> (-26.1816, 85)
extrude "Extrude67" cut sketch "Support-free horizontal rail hole roof (1)" along normal blind 9.2
work_plane "WorkPlane61" AlongDistance 54.9 ExtraOffset 0
sketch "Support-free horizontal rail hole roof" plane through (0, 0, 54.9) normal (0, 0, 1) x axis (1, 0, 0)
  line L1 (31.9092, -83.0908) -> (31.9092, -86.9092)
  line L2 (33.8184, -85) -> (31.9092, -83.0908)
  line L3 (31.9092, -86.9092) -> (33.8184, -85)
extrude "Extrude61" cut sketch "Support-free horizontal rail hole roof" along normal blind 9.2
work_plane "WorkPlane62" AlongDistance 54.9 ExtraOffset 0
sketch "Support-free horizontal rail hole roof (1)" plane through (0, 0, 54.9) normal (0, 0, 1) x axis (1, 0, 0)
  line L1 (31.9092, 86.9092) -> (31.9092, 83.0908)
  line L2 (33.8184, 85) -> (31.9092, 86.9092)
  line L3 (31.9092, 83.0908) -> (33.8184, 85)
extrude "Extrude62" cut sketch "Support-free horizontal rail hole roof (1)" along normal blind 9.2
work_plane "WorkPlane14" AlongDistance 4 ExtraOffset 0
sketch "Reinforced roof over support-free pivot bore" plane through (4, 0, 0) normal (1, 0, 0) x axis (0, 0, -1)
  line L1 (-17.9, -29) -> (-17.9, -41)
  line L2 (-20, -29) -> (-17.9, -29)
  line L3 (-20, -41) -> (-20, -29)
  line L4 (-17.9, -41) -> (-20, -41)
extrude "Extrude14" add sketch "Reinforced roof over support-free pivot bore" along normal blind 3
work_plane "WorkPlane15" AlongDistance 4 ExtraOffset 0
sketch "Flat print foot below roller cheek" plane through (4, 0, 0) normal (1, 0, 0) x axis (0, 0, -1)
  line L1 (-6, 6) -> (-6, -6)
  line L2 (-12, 6) -> (-6, 6)
  line L3 (-12, -6) -> (-12, 6)
  line L4 (-6, -6) -> (-12, -6)
extrude "Extrude15" add sketch "Flat print foot below roller cheek" along normal blind 3
work_plane "WorkPlane16" AlongDistance 17 ExtraOffset 0
sketch "Reinforced roof over support-free pivot bore (1)" plane through (17, 0, 0) normal (1, 0, 0) x axis (0, 0, -1)
  line L1 (-17.9, -29) -> (-17.9, -41)
  line L2 (-20, -29) -> (-17.9, -29)
  line L3 (-20, -41) -> (-20, -29)
  line L4 (-17.9, -41) -> (-20, -41)
extrude "Extrude16" add sketch "Reinforced roof over support-free pivot bore (1)" along normal blind 3
work_plane "WorkPlane17" AlongDistance 17 ExtraOffset 0
sketch "Flat print foot below roller cheek (1)" plane through (17, 0, 0) normal (1, 0, 0) x axis (0, 0, -1)
  line L1 (-6, 6) -> (-6, -6)
  line L2 (-12, 6) -> (-6, 6)
  line L3 (-12, -6) -> (-12, 6)
  line L4 (-6, -6) -> (-12, -6)
extrude "Extrude17" add sketch "Flat print foot below roller cheek (1)" along normal blind 3
work_plane "WorkPlane18" AlongDistance 3.9 ExtraOffset 0
sketch "Follower horizontal bore 45 degree roof" plane through (3.9, 0, 0) normal (1, 0, 0) x axis (0, 0, -1)
  line L1 (-14.9345, -32.0655) -> (-14.9345, -37.9345)
  line L2 (-17.869, -35) -> (-14.9345, -32.0655)
  line L3 (-14.9345, -37.9345) -> (-17.869, -35)
extrude "Extrude18" cut sketch "Follower horizontal bore 45 degree roof" along normal blind 16.2
work_plane "WorkPlane19" AlongDistance 3.9 ExtraOffset 0
sketch "Follower horizontal bore 45 degree roof (1)" plane through (3.9, 0, 0) normal (1, 0, 0) x axis (0, 0, -1)
  line L1 (-13.2021, 1.2021) -> (-13.2021, -1.2021)
  line L2 (-14.4042, 0) -> (-13.2021, 1.2021)
  line L3 (-13.2021, -1.2021) -> (-14.4042, 0)
extrude "Extrude19" cut sketch "Follower horizontal bore 45 degree roof (1)" along normal blind 16.2
work_plane "WorkPlane11" AlongDistance 9 ExtraOffset 0
sketch "Upright grip head pocket roof" plane through (9, 0, 0) normal (1, 0, 0) x axis (0, 0, -1)
  line L1 (-182.192, -2.192) -> (-182.192, 2.192)
  line L2 (-184.3841, 0) -> (-182.192, -2.192)
  line L3 (-182.192, 2.192) -> (-184.3841, 0)
extrude "Extrude10" cut sketch "Upright grip head pocket roof" along normal blind 16
work_plane "WorkPlane12" AlongDistance 9 ExtraOffset 0
sketch "Upright grip head pocket roof (1)" plane through (9, 0, 0) normal (1, 0, 0) x axis (0, 0, -1)
  line L1 (-192.192, -2.192) -> (-192.192, 2.192)
  line L2 (-194.3841, 0) -> (-192.192, -2.192)
  line L3 (-192.192, 2.192) -> (-194.3841, 0)
extrude "Extrude11" cut sketch "Upright grip head pocket roof (1)" along normal blind 16
work_plane "WorkPlane1" AlongDistance -4.5 ExtraOffset 0
sketch "Shaft joining M3x8 -15" plane through (0, -4.5, 0) normal (0, 1, 0) x axis (1, 0, 0)
  circle C1 centre (-15, -65) radius 1.5
extrude "Extrude1" new body sketch "Shaft joining M3x8 -15" along normal blind 8 bodies "HARDWARE Shaft joining M3x8 -15"
work_plane "WorkPlane2" AlongDistance 3.5 ExtraOffset 0
sketch "Button head" plane through (0, 3.5, 0) normal (0, 1, 0) x axis (1, 0, 0)
  circle C1 centre (-15, -65) radius 2.75
extrude "Extrude2" add sketch "Button head" along normal blind 3
work_plane "WorkPlane1" AlongDistance -4.5 ExtraOffset 0
sketch "Shaft joining M3x8 15" plane through (0, -4.5, 0) normal (0, 1, 0) x axis (1, 0, 0)
  circle C1 centre (15, -65) radius 1.5
extrude "Extrude1" new body sketch "Shaft joining M3x8 15" along normal blind 8 bodies "HARDWARE Shaft joining M3x8 15"
work_plane "WorkPlane2" AlongDistance 3.5 ExtraOffset 0
sketch "Button head" plane through (0, 3.5, 0) normal (0, 1, 0) x axis (1, 0, 0)
  circle C1 centre (15, -65) radius 2.75
extrude "Extrude2" add sketch "Button head" along normal blind 3
work_plane "WorkPlane1" AlongDistance -6.5 ExtraOffset 0
sketch "Loose flat printable alignment key" plane through (-6.5, 0, 0) normal (1, 0, 0) x axis (0, 0, -1)
  line L1 (-61.1, 1.5) -> (-61.1, -1.5)
  line L2 (-68.9, 1.5) -> (-61.1, 1.5)
  line L3 (-68.9, -1.5) -> (-68.9, 1.5)
  line L4 (-61.1, -1.5) -> (-68.9, -1.5)
extrude "Extrude1" new body sketch "Loose flat printable alignment key" along normal blind 3 bodies "P28 Shaft alignment key -5"
work_plane "WorkPlane1" AlongDistance 3.5 ExtraOffset 0
sketch "Loose flat printable alignment key" plane through (3.5, 0, 0) normal (1, 0, 0) x axis (0, 0, -1)
  line L1 (-61.1, 1.5) -> (-61.1, -1.5)
  line L2 (-68.9, 1.5) -> (-61.1, 1.5)
  line L3 (-68.9, -1.5) -> (-68.9, 1.5)
  line L4 (-61.1, -1.5) -> (-68.9, -1.5)
extrude "Extrude1" new body sketch "Loose flat printable alignment key" along normal blind 3 bodies "P28 Shaft alignment key 5"
work_plane "WorkPlane19" AlongDistance -5 ExtraOffset 0
sketch "Direct cap-head rotor clamp seat" plane through (-5, 0, 0) normal (1, 0, 0) x axis (0, 0, -1)
  line L1 (-60, 22.5) -> (-60, 22)
  line L2 (-70, 22.5) -> (-60, 22.5)
  line L3 (-70, 22) -> (-70, 22.5)
  line L4 (-60, 22) -> (-70, 22)
extrude "Extrude19" add sketch "Direct cap-head rotor clamp seat" along normal blind 10
work_plane "WorkPlane20" AlongDistance 21.9 ExtraOffset 0
sketch "Restore rotor screw through raised seat" plane through (0, 21.9, 0) normal (0, 1, 0) x axis (1, 0, 0)
  circle C1 centre (0, -65) radius 1.7
extrude "Extrude20" cut sketch "Restore rotor screw through raised seat" along normal blind 0.7
work_plane "WorkPlane1" AlongDistance -39.35 ExtraOffset 0
sketch "Main shaft cap M3x8 cap head" plane through (-39.35, 0, 0) normal (1, 0, 0) x axis (0, 0, -1)
  circle C1 centre (-65, 0) radius 1.5
extrude "Extrude1" new body sketch "Main shaft cap M3x8 cap head" along normal blind 8 bodies "HARDWARE Main shaft cap M3x8 cap head"
work_plane "WorkPlane2" AlongDistance -42.35 ExtraOffset 0
sketch "Button head" plane through (-42.35, 0, 0) normal (1, 0, 0) x axis (0, 0, -1)
  circle C1 centre (-65, 0) radius 2.75
extrude "Extrude2" add sketch "Button head" along normal blind 3
work_plane "WorkPlane1" AlongDistance 2 ExtraOffset 0
sketch "Cam M3x10 cap head -45" plane through (2, 0, 0) normal (1, 0, 0) x axis (0, 0, -1)
  circle C1 centre (-39.5442, 25.4558) radius 1.5
extrude "Extrude1" new body sketch "Cam M3x10 cap head -45" along normal blind 10 bodies "HARDWARE Cam M3x10 cap head -45"
work_plane "WorkPlane2" AlongDistance 12 ExtraOffset 0
sketch "Button head" plane through (12, 0, 0) normal (1, 0, 0) x axis (0, 0, -1)
  circle C1 centre (-39.5442, 25.4558) radius 2.75
extrude "Extrude2" add sketch "Button head" along normal blind 3
work_plane "WorkPlane1" AlongDistance 2 ExtraOffset 0
sketch "Cam M3x10 cap head 0" plane through (2, 0, 0) normal (1, 0, 0) x axis (0, 0, -1)
  circle C1 centre (-29, 0) radius 1.5
extrude "Extrude1" new body sketch "Cam M3x10 cap head 0" along normal blind 10 bodies "HARDWARE Cam M3x10 cap head 0"
work_plane "WorkPlane2" AlongDistance 12 ExtraOffset 0
sketch "Button head" plane through (12, 0, 0) normal (1, 0, 0) x axis (0, 0, -1)
  circle C1 centre (-29, 0) radius 2.75
extrude "Extrude2" add sketch "Button head" along normal blind 3
work_plane "WorkPlane1" AlongDistance 2 ExtraOffset 0
sketch "Cam M3x10 cap head 45" plane through (2, 0, 0) normal (1, 0, 0) x axis (0, 0, -1)
  circle C1 centre (-39.5442, -25.4558) radius 1.5
extrude "Extrude1" new body sketch "Cam M3x10 cap head 45" along normal blind 10 bodies "HARDWARE Cam M3x10 cap head 45"
work_plane "WorkPlane2" AlongDistance 12 ExtraOffset 0
sketch "Button head" plane through (12, 0, 0) normal (1, 0, 0) x axis (0, 0, -1)
  circle C1 centre (-39.5442, -25.4558) radius 2.75
extrude "Extrude2" add sketch "Button head" along normal blind 3
work_plane "WorkPlane1" AlongDistance 0 ExtraOffset 0
sketch "Roller axle M3x20 cap head" plane through (0, 0, 0) normal (1, 0, 0) x axis (0, 0, -1)
  circle C1 centre (-12, 0) radius 1.5
extrude "Extrude1" new body sketch "Roller axle M3x20 cap head" along normal blind 20 bodies "HARDWARE Roller axle M3x20 cap head"
work_plane "WorkPlane2" AlongDistance 20 ExtraOffset 0
sketch "Button head" plane through (20, 0, 0) normal (1, 0, 0) x axis (0, 0, -1)
  circle C1 centre (-12, 0) radius 2.75
extrude "Extrude2" add sketch "Button head" along normal blind 3
work_plane "WorkPlane1" AlongDistance -36 ExtraOffset 0
sketch "Crossblock M3x20 cap head (-62, -1)" plane through (-36, 0, 0) normal (1, 0, 0) x axis (0, 0, -1)
  circle C1 centre (-53.5, -62) radius 1.5
extrude "Extrude1" new body sketch "Crossblock M3x20 cap head (-62, -1)" along normal blind 20 bodies "HARDWARE Crossblock M3x20 cap head (-62, -1)"
work_plane "WorkPlane2" AlongDistance -39 ExtraOffset 0
sketch "Button head" plane through (-39, 0, 0) normal (1, 0, 0) x axis (0, 0, -1)
  circle C1 centre (-53.5, -62) radius 2.75
extrude "Extrude2" add sketch "Button head" along normal blind 3
work_plane "WorkPlane1" AlongDistance 16 ExtraOffset 0
sketch "Crossblock M3x20 cap head (-62, 1)" plane through (16, 0, 0) normal (1, 0, 0) x axis (0, 0, -1)
  circle C1 centre (-53.5, -62) radius 1.5
extrude "Extrude1" new body sketch "Crossblock M3x20 cap head (-62, 1)" along normal blind 20 bodies "HARDWARE Crossblock M3x20 cap head (-62, 1)"
work_plane "WorkPlane2" AlongDistance 36 ExtraOffset 0
sketch "Button head" plane through (36, 0, 0) normal (1, 0, 0) x axis (0, 0, -1)
  circle C1 centre (-53.5, -62) radius 2.75
extrude "Extrude2" add sketch "Button head" along normal blind 3
work_plane "WorkPlane1" AlongDistance -36 ExtraOffset 0
sketch "Crossblock M3x20 cap head (-70, -1)" plane through (-36, 0, 0) normal (1, 0, 0) x axis (0, 0, -1)
  circle C1 centre (-53.5, -70) radius 1.5
extrude "Extrude1" new body sketch "Crossblock M3x20 cap head (-70, -1)" along normal blind 20 bodies "HARDWARE Crossblock M3x20 cap head (-70, -1)"
work_plane "WorkPlane2" AlongDistance -39 ExtraOffset 0
sketch "Button head" plane through (-39, 0, 0) normal (1, 0, 0) x axis (0, 0, -1)
  circle C1 centre (-53.5, -70) radius 2.75
extrude "Extrude2" add sketch "Button head" along normal blind 3
work_plane "WorkPlane1" AlongDistance 16 ExtraOffset 0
